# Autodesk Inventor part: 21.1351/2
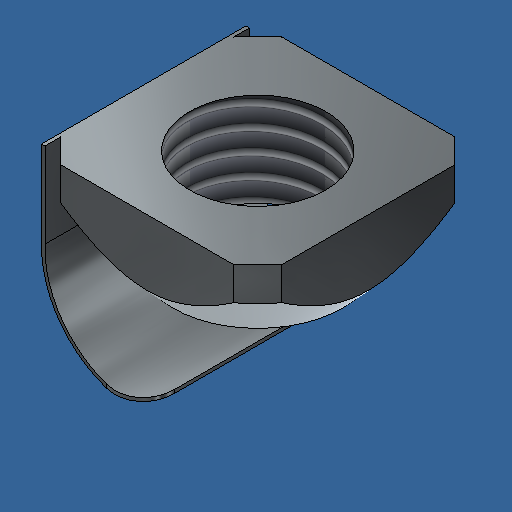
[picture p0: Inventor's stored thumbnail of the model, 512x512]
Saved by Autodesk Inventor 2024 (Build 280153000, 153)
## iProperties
Created: 2006-12
Part Number: 21.1351/2
Document SubType Name: Modeling
Designer: Andy Moles
Material: Steel, Mild
Density: 7.85 g/cm^3
Mass: 4.24899 g
Surface Area: 8.34272 cm^2
Volume: 0.541273 cm^3
Description: M8 SQUARE NUT POS FXG
Vendor: S
Appearance: Zinc
Title: M8 SQUARE NUT POS FXG
Author: Andy Moles
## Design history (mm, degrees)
sketch "Sketch2"
  geometry: L1 (-5.086, -6.5)-(5.086, -6.5); L2 (6.5, -5.086)-(6.5, 5.086); L3 (5.086, 6.5)-(-5.086, 6.5); L4 (-6.5, 5.086)-(-6.5, -5.086); L5 (-6.5, 6.5)-(6.5, -6.5); L6 (5.086, 6.5)-(6.5, 5.086); L7 (0, -6.5)-(0, 6.5); L8 (-6.5, 0)-(6.5, 0); L9 (-5.086, 6.5)-(-6.5, 5.086); L10 (-5.086, -6.5)-(-6.5, -5.086); L11 (5.086, -6.5)-(6.5, -5.086); C1 r 4 at (0, 0); 2 further points
  constraints: 22 end point, 6 symmetric about line, 4 parallel, 3 midpoint, 2 coincident, 2 perpendicular, 1 centre point, 1 horizontal
  dimensions: "THREAD" = 8 diameter of C1; "d3" = 45 deg angle of L3 L6 (derived); "d4" = 2 distance of L3.start L2.end
extrude "Extrusion1" new body sketch "Sketch2" distance "d5" = 5.5; taper "d6" = 0 deg
workplane "Work Plane1"
sketch "Sketch4"
  geometry: L1 (12.192, 0)-(4.192, 0) reference; L2 (8.192, 0)-(13.192, 0); L3 (16.385, 5.5)-(16.385, 3.5); L4 (13.192, 0)-(16.797, 3.952); L5 (13.192, 0)-(16.385, 0); L6 (16.385, 3.5)-(16.385, 0); L7 (16.797, 3.952)-(16.797, -0.412); L8 (16.797, -0.412)-(13.192, -0.412); L9 (13.192, -0.412)-(13.192, 0); L10 (8.192, 5.5)-(8.192, 0); L11 (16.385, 5.5)-(16.385, 0) reference; L12 (16.385, 3.5)-(17.502, 3.5); L13 (9.192, 5.5)-(16.385, 5.5) reference
  constraints: 20 end point, 6 perpendicular, 1 collinear, 1 midpoint, 1 parallel, 1 point on line
  dimensions: "d10" = 5 distance of L2.start L2.end; "d15" = 2 distance between parallel lines of L12 L13
revolve "Revolution1" sketch "Sketch4" stored, may be unused: angle "d12" = 90 deg
thread "Thread1" dims "d13" = 10, "d14" = 0
sketch "Sketch6"
  geometry: L1 (2.954, -2.535)-(2.954, 6.006); L2 (2.954, -2.535)-(2.954, -7.535); L3 (2.954, -2.535)-(3.154, -2.535); L4 (3.154, -2.535)-(3.154, -7.535); L5 (-2.646, -13.135)-(-2.646, -13.335); L6 (2.954, 0)-(2.954, -1.933); L7 (-8.632, -2.535)-(1.539, -2.535) reference; L8 (2.954, -2.535)-(2.954, -4.468) reference; A1 r 5.374 centre (-2.416, -7.766) between (-2.646, -13.135) and (2.954, -7.535); A2 r 5.574 centre (-2.416, -7.766) between (-2.646, -13.335) and (3.154, -7.535); 4 further points; 1 other entity
  constraints: 12 end point, 4 point on circle, 3 collinear, 2 centre point, 2 horizontal, 2 parallel, 2 perpendicular, 1 coincident, 3 other
  dimensions: "d25" = 5 distance of L1.start L2.end; "d23" = 0.2 distance of L1.start L3.end; "d22" = 0.2 distance of L5.start L5.end; "d21" = 10.8 distance from line of L5.end L3; "d24" = 5.37434 radius of A1
extrude "Extrusion3" join sketch "Sketch6" taper "d27" = 0 deg; stored distance "d28" = 12
fillet "Fillet2" dims "d29" = 2
body "Solid1"
